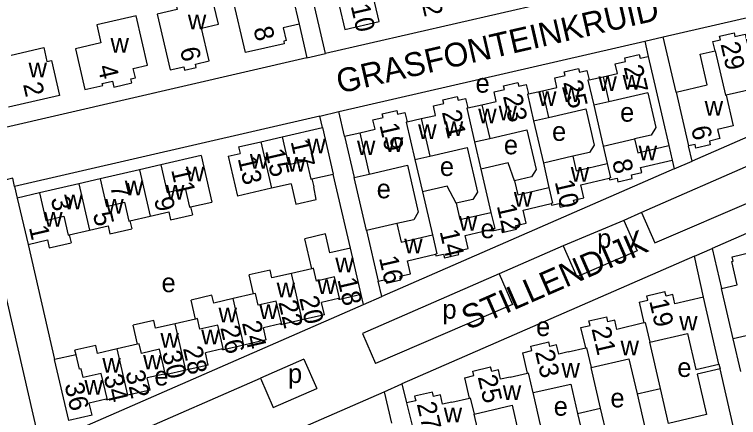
# Model space of a CAD drawing. Extents: x 155696 to 157795, y 382328 to 384028.
# Drawn here: x 157023.6 to 157175.4, y 383530 to 383614.6 of the extents above; entities that cross this region are included whole.
import ezdxf

# ---------------------------------------------------------------- set-up
doc = ezdxf.new("R2010")
doc.units = 0
for name, color, linetype in [('BLT_Basislijn', 7, 'Continuous'), ('BLT_Bebouwing', 7, 'Continuous'), ('BLT_Centroide', 7, 'Continuous'), ('BLT_Huisnummer', 7, 'Continuous'), ('BLT_Huisnummer_ tussenligend', 7, 'Continuous'), ('BLT_Onderverdeling_panden', 7, 'Continuous'), ('BLT_Straatnaam', 7, 'Continuous')]:
    doc.layers.add(name, color=color, linetype=linetype)

msp = doc.modelspace()

# ---------------------------------------------------------------- linework, layer by layer
at = {"layer": 'BLT_Basislijn'}
for p, q in [((157155.73, 383609.02), (157159.62, 383609.92)), ((157084.93, 383605.5), (157088.83, 383606.4)), ((157208.37, 383596.51), (157155.06, 383573.01)), ((157087.64, 383593.29), (157091.64, 383594.22)), ((157157.85, 383566.64), (157211.33, 383589.75)), ((157161.92, 383582.21), (157165.65, 383583.84)), ((157155.06, 383573.01), (157151.34, 383571.38)), ((157155.06, 383573.01), (157157.85, 383566.64)), ((157151.34, 383571.38), (157138.66, 383566.03)), ((157151.34, 383571.38), (157154.12, 383565.02)), ((157026.48, 383566.34), (157032.06, 383542.16)), ((157138.66, 383566.03), (157125.24, 383560.16)), ((157138.66, 383566.03), (157141.48, 383559.56)), ((157154.12, 383565.02), (157141.48, 383559.56)), ((157166.15, 383563.87), (157169.88, 383565.5)), ((157125.24, 383560.16), (157128.04, 383553.76)), ((157096.77, 383553.76), (157100.61, 383555.4)), ((157128.04, 383553.76), (157099.33, 383541.35)), ((157096.59, 383547.63), (157099.33, 383541.35)), ((157175.89, 383539.68), (157174.29, 383546.5)), ((157084.31, 383542.27), (157075.18, 383538.27)), ((157084.31, 383542.27), (157087.02, 383536.08)), ((157171.29, 383541.21), (157171.53, 383540.21)), ((157044.35, 383524.79), (157075.18, 383538.27)), ((157075.18, 383538.27), (157077.89, 383532.08)), ((157101.12, 383535.43), (157104.85, 383537.06)), ((157077.89, 383532.08), (157087.02, 383536.08))]:
    msp.add_line(p, q, dxfattribs=at)
for points in [[(157088.83, 383606.4), (157076, 383661.94)], [(157159.62, 383609.92), (157231.49, 383626.52)], [(157152.91, 383621.2), (157088.83, 383606.4)], [(157234.4, 383613.91), (157165.65, 383583.84), (157164.91, 383587.02)], [(157083.3, 383612.59), (157084.93, 383605.5)], [(157162.3, 383598.33), (157159.62, 383609.92)], [(157091.64, 383594.22), (157155.73, 383609.02)], [(157155.73, 383609.02), (157156.47, 383605.81)], [(157084.93, 383605.5), (157020.85, 383590.7)], [(157238.64, 383595.57), (157169.88, 383565.5), (157171.84, 383557.12)], [(157087.64, 383593.29), (157023.66, 383578.52)], [(157088.2, 383590.86), (157087.64, 383593.29)], [(157092.84, 383589.03), (157091.64, 383594.22)], [(157161.49, 383584.05), (157161.92, 383582.21)], [(157094.04, 383565.57), (157090.45, 383581.11)], [(157161.92, 383582.21), (157100.61, 383555.4)], [(157023.66, 383578.52), (157023.27, 383580.23), (157022.19, 383579.96), (157021.34, 383579.68), (157020.04, 383578.87), (157018.83, 383577.79), (157018.05, 383576.3), (157017.68, 383574.81), (157017.8, 383572.79), (157028.71, 383525.55)], [(157097.41, 383569.25), (157094.84, 383580.38)], [(157023.66, 383578.52), (157024.23, 383576.08)], [(157166.15, 383563.87), (157104.85, 383537.06)], [(157168.04, 383555.27), (157166.15, 383563.87)], [(157125.24, 383560.16), (157096.59, 383547.63)], [(157100.61, 383555.4), (157099.86, 383558.63)], [(157035.57, 383526.96), (157096.77, 383553.76), (157096.29, 383555.83)], [(157104.85, 383537.06), (157105.83, 383533.1)], [(157039.81, 383508.62), (157101.12, 383535.43), (157102.64, 383528.81)]]:
    msp.add_lwpolyline(points, dxfattribs=at)
at = {"layer": 'BLT_Bebouwing'}
for p, q in [((157079.91, 383627.27), (157083.3, 383612.59)), ((157022.95, 383606.06), (157029.77, 383607.64)), ((157029.77, 383607.64), (157030.44, 383604.71)), ((157030.44, 383604.71), (157031.42, 383604.94)), ((157031.42, 383604.94), (157033.1, 383597.63)), ((157048.55, 383603.25), (157051.53, 383603.94)), ((157049, 383601.3), (157048.55, 383603.25)), ((157048.05, 383601.08), (157049, 383601.3)), ((157048.25, 383600.23), (157048.05, 383601.08)), ((157038.4, 383598.85), (157042.14, 383599.72)), ((157042.04, 383600.12), (157044.17, 383600.61)), ((157042.14, 383599.72), (157042.04, 383600.12)), ((157044.17, 383600.61), (157044.46, 383599.35)), ((157044.46, 383599.35), (157048.25, 383600.23)), ((157033.1, 383597.63), (157022.39, 383595.15)), ((157162.3, 383598.33), (157164.91, 383587.02)), ((157145.05, 383595.57), (157147.04, 383586.97)), ((157132.45, 383592.25), (157134.49, 383583.41)), ((157079.76, 383588.91), (157088.2, 383590.86)), ((157088.2, 383590.86), (157090.45, 383581.11)), ((157075.29, 383587.87), (157079.76, 383588.91)), ((157070.61, 383586.8), (157075.29, 383587.87)), ((157120.09, 383587.86), (157121.41, 383582.15)), ((157070.61, 383586.8), (157070.93, 383585.43)), ((157062.77, 383584.98), (157054.33, 383583.03)), ((157062.77, 383584.98), (157065.02, 383575.24)), ((157068.44, 383584.86), (157070.93, 383585.43)), ((157068.44, 383584.86), (157070.38, 383576.48)), ((157107.57, 383584.15), (157109.14, 383577.37)), ((157054.33, 383583.03), (157049.86, 383582)), ((157049.86, 383582), (157041.61, 383580.1)), ((157085.98, 383580.08), (157090.45, 383581.11)), ((157041.61, 383580.1), (157037.14, 383579.06)), ((157085.98, 383580.08), (157086.36, 383578.43)), ((157037.14, 383579.06), (157028.9, 383577.16)), ((157077.54, 383578.13), (157070.38, 383576.48)), ((157081.64, 383579.08), (157077.54, 383578.13)), ((157086.9, 383575.78), (157086.36, 383578.43)), ((157028.9, 383577.16), (157024.23, 383576.08)), ((157024.23, 383576.08), (157026.48, 383566.34)), ((157060.55, 383574.21), (157065.02, 383575.24)), ((157060.55, 383574.21), (157060.93, 383572.56)), ((157047.83, 383571.27), (157052.11, 383572.26)), ((157052.11, 383572.26), (157055.99, 383573.15)), ((157055.99, 383573.15), (157056.37, 383571.51)), ((157056.37, 383571.51), (157060.93, 383572.56)), ((157047.83, 383571.27), (157048.21, 383569.62)), ((157035.12, 383568.33), (157039.39, 383569.32)), ((157039.39, 383569.32), (157043.28, 383570.22)), ((157043.28, 383570.22), (157043.66, 383568.57)), ((157043.66, 383568.57), (157048.21, 383569.62)), ((157026.48, 383566.34), (157030.56, 383567.28)), ((157030.56, 383567.28), (157030.94, 383565.63)), ((157035.12, 383568.33), (157035.5, 383566.69)), ((157088.86, 383568.53), (157084.52, 383567.52)), ((157085.94, 383561.24), (157084.52, 383567.52)), ((157089.76, 383564.58), (157088.86, 383568.53)), ((157030.94, 383565.63), (157035.5, 383566.69)), ((157094.04, 383565.57), (157089.76, 383564.58)), ((157096.29, 383555.83), (157094.04, 383565.57)), ((157085.94, 383561.24), (157081.67, 383560.25)), ((157077.2, 383560.95), (157072.84, 383559.94)), ((157073.77, 383555.96), (157072.84, 383559.94)), ((157077.58, 383559.3), (157077.2, 383560.95)), ((157081.67, 383560.25), (157077.58, 383559.3)), ((157174.29, 383546.5), (157171.84, 383557.12)), ((157065.02, 383555.68), (157060.67, 383554.67)), ((157065.41, 383554.03), (157065.02, 383555.68)), ((157073.77, 383555.96), (157069.49, 383554.97)), ((157096.29, 383555.83), (157091.82, 383554.79)), ((157061.59, 383550.68), (157060.67, 383554.67)), ((157069.49, 383554.97), (157065.41, 383554.03)), ((157091.57, 383554.96), (157088, 383554.14)), ((157088.59, 383551.58), (157088, 383554.14)), ((157091.62, 383554.75), (157091.57, 383554.96)), ((157091.82, 383554.79), (157091.62, 383554.75)), ((157061.59, 383550.68), (157057.32, 383549.7)), ((157088.59, 383551.58), (157083.92, 383550.51)), ((157052.85, 383550.4), (157048.49, 383549.39)), ((157049.42, 383545.41), (157048.49, 383549.39)), ((157053.23, 383548.75), (157052.85, 383550.4)), ((157057.32, 383549.7), (157053.23, 383548.75)), ((157079.4, 383549.69), (157075.83, 383548.86)), ((157079.45, 383549.47), (157079.4, 383549.69)), ((157079.65, 383549.52), (157079.45, 383549.47)), ((157083.92, 383550.51), (157079.65, 383549.52)), ((157076.42, 383546.31), (157075.83, 383548.86)), ((157076.42, 383546.31), (157071.74, 383545.23)), ((157040.67, 383545.12), (157036.32, 383544.12)), ((157041.06, 383543.48), (157040.67, 383545.12)), ((157049.42, 383545.41), (157045.14, 383544.42)), ((157071.74, 383545.23), (157067.47, 383544.24)), ((157036.55, 383543.2), (157032.06, 383542.16)), ((157036.55, 383543.2), (157036.32, 383544.12)), ((157045.14, 383544.42), (157041.06, 383543.48)), ((157067.22, 383544.41), (157063.65, 383543.59)), ((157064.24, 383541.03), (157063.65, 383543.59)), ((157067.27, 383544.2), (157067.22, 383544.41)), ((157067.47, 383544.24), (157067.27, 383544.2)), ((157035.02, 383529.36), (157032.06, 383542.16)), ((157059.57, 383539.95), (157055.3, 383538.97)), ((157064.24, 383541.03), (157059.57, 383539.95)), ((157055.05, 383539.14), (157051.48, 383538.31)), ((157055.1, 383538.92), (157055.05, 383539.14)), ((157055.3, 383538.97), (157055.1, 383538.92)), ((157052.07, 383535.76), (157051.48, 383538.31)), ((157052.07, 383535.76), (157047.39, 383534.68)), ((157047.39, 383534.68), (157043.12, 383533.69)), ((157042.87, 383533.86), (157039.3, 383533.03)), ((157039.89, 383530.48), (157039.3, 383533.03)), ((157042.92, 383533.65), (157042.87, 383533.86)), ((157043.12, 383533.69), (157042.92, 383533.65)), ((157105.83, 383533.1), (157107.72, 383525.43)), ((157039.89, 383530.48), (157035.02, 383529.36))]:
    msp.add_line(p, q, dxfattribs=at)
msp.add_lwpolyline([(157100.36, 383629.56), (157096.13, 383628.59), (157097.03, 383624.7), (157089.29, 383622.91), (157090.81, 383616.32), (157091.69, 383616.52), (157092.86, 383611.43), (157100.06, 383613.1), (157098.26, 383620.89), (157102.16, 383621.79)], close=True, dxfattribs=at)
for points in [[(157083.3, 383612.59), (157079.99, 383611.83), (157080.59, 383609.14), (157080.07, 383609.01), (157080.2, 383608.46), (157072.04, 383606.6), (157069.34, 383618.31), (157073.62, 383619.3), (157072.61, 383623.68), (157076.17, 383624.5), (157075.75, 383626.31), (157079.91, 383627.27)], [(157064.42, 383604.86), (157062.83, 383611.72), (157066.37, 383612.54), (157064.41, 383621), (157056.92, 383619.26), (157057.76, 383615.62), (157053.58, 383614.65), (157056.28, 383602.98), (157059.13, 383603.64), (157059.3, 383602.89), (157061.74, 383603.45), (157061.57, 383604.2), (157064.42, 383604.86)], [(157049.13, 383614.31), (157040.87, 383612.4), (157041.74, 383608.65), (157036.42, 383607.42), (157038.4, 383598.85)], [(157051.53, 383603.94), (157049.13, 383614.31)], [(157170.47, 383606.99), (157170.02, 383608.94), (157171.61, 383609.3), (157171.43, 383610.08), (157174.45, 383610.78), (157174.63, 383610), (157176.78, 383610.5), (157177.23, 383608.55), (157180.24, 383609.25), (157181.08, 383605.64)], [(157162.3, 383598.33), (157168.85, 383599.84), (157167.36, 383606.27), (157170.47, 383606.99)], [(157147, 383601.54), (157150.03, 383602.24), (157149.57, 383604.21), (157151.73, 383604.71), (157151.55, 383605.49), (157154.57, 383606.19), (157154.75, 383605.41), (157156.47, 383605.81)], [(157156.47, 383605.81), (157158.13, 383598.6)], [(157134.31, 383598.61), (157137.33, 383599.3), (157136.87, 383601.28), (157139.03, 383601.78), (157138.85, 383602.56), (157141.87, 383603.25), (157142.05, 383602.48), (157143.61, 383602.84), (157144.06, 383600.86)], [(157144.06, 383600.86), (157147, 383601.54)], [(157121.61, 383595.67), (157124.62, 383596.37), (157124.16, 383598.34), (157126.32, 383598.84), (157126.14, 383599.62), (157129.16, 383600.32), (157129.34, 383599.54), (157130.9, 383599.9), (157131.36, 383597.92)], [(157131.36, 383597.92), (157134.31, 383598.61)], [(157156.38, 383598.19), (157148.21, 383596.3)], [(157156.38, 383598.19), (157158.07, 383590.86), (157157.1, 383589.3), (157153.59, 383588.49)], [(157158.13, 383598.6), (157160.8, 383587.07)], [(157172.82, 383597.68), (157174.3, 383591.25), (157171, 383590.48), (157171.45, 383588.54), (157169.3, 383588.04), (157169.48, 383587.26), (157166.46, 383586.56), (157166.28, 383587.34), (157164.91, 383587.02)], [(157182.98, 383595.46), (157179.66, 383594.69), (157178.65, 383599.02), (157172.82, 383597.68)], [(157108.91, 383592.74), (157111.91, 383593.43), (157111.46, 383595.41), (157113.62, 383595.91), (157113.44, 383596.69), (157116.46, 383597.39), (157116.64, 383596.61), (157118.2, 383596.97), (157118.65, 383594.99)], [(157148.21, 383596.3), (157145.05, 383595.57)], [(157118.65, 383594.99), (157121.61, 383595.67)], [(157135.6, 383592.98), (157143.39, 383594.78)], [(157143.39, 383594.78), (157145.14, 383587.2), (157144.17, 383585.64), (157140.66, 383584.83)], [(157096, 383589.76), (157099.21, 383590.5), (157098.75, 383592.47), (157100.91, 383592.97), (157100.73, 383593.75), (157103.75, 383594.45), (157103.93, 383593.67), (157105.49, 383594.03), (157105.95, 383592.05)], [(157105.95, 383592.05), (157108.91, 383592.74)], [(157132.45, 383592.25), (157135.6, 383592.98)], [(157123.25, 383588.59), (157131.03, 383590.39)], [(157131.03, 383590.39), (157132.95, 383582.08), (157131.98, 383580.52), (157128.47, 383579.71)], [(157092.84, 383589.03), (157096, 383589.76)], [(157092.84, 383589.03), (157094.84, 383580.38)], [(157120.09, 383587.86), (157123.25, 383588.59)], [(157147.04, 383586.97), (157153.59, 383588.49)], [(157160.8, 383587.07), (157161.49, 383584.05)], [(157110.73, 383584.88), (157118.52, 383586.67)], [(157118.52, 383586.67), (157120.67, 383577.34), (157119.7, 383575.78), (157116.19, 383574.97)], [(157107.57, 383584.15), (157110.73, 383584.88)], [(157140.66, 383584.83), (157134.49, 383583.41)], [(157148.26, 383580.23), (157148.34, 383579.88), (157149.93, 383580.25), (157150.11, 383579.47), (157153.13, 383580.17), (157152.95, 383580.95), (157155.11, 383581.45), (157154.86, 383582.52), (157161.49, 383584.05)], [(157098, 383581.11), (157106, 383582.96)], [(157106, 383582.96), (157108.28, 383573.09), (157107.31, 383571.53), (157103.8, 383570.72)], [(157128.47, 383579.71), (157127.12, 383583.46), (157121.41, 383582.15)], [(157094.84, 383580.38), (157098, 383581.11)], [(157136.14, 383574.91), (157136.22, 383574.57), (157137.81, 383574.94), (157137.99, 383574.16), (157141.01, 383574.86), (157140.83, 383575.63), (157142.99, 383576.13), (157142.36, 383578.86), (157148.26, 383580.23)], [(157081.64, 383579.08), (157082.63, 383574.79), (157086.9, 383575.78)], [(157116.19, 383574.97), (157114.35, 383578.58), (157109.14, 383577.37)], [(157124.02, 383569.6), (157124.1, 383569.26), (157125.69, 383569.62), (157125.87, 383568.84), (157128.89, 383569.54), (157128.71, 383570.32), (157130.87, 383570.82), (157130.24, 383573.55), (157136.14, 383574.91)], [(157103.8, 383570.72), (157097.41, 383569.25)], [(157097.41, 383569.25), (157099.86, 383558.63)], [(157111.9, 383564.28), (157111.98, 383563.94), (157113.57, 383564.31), (157113.75, 383563.53), (157116.77, 383564.23), (157116.59, 383565.01), (157118.75, 383565.5), (157118.12, 383568.23), (157124.02, 383569.6)], [(157099.86, 383558.63), (157101.45, 383558.99), (157101.63, 383558.22), (157104.65, 383558.91), (157104.47, 383559.69), (157106.63, 383560.19), (157106, 383562.92), (157111.9, 383564.28)], [(157171.84, 383557.12), (157175.12, 383557.87), (157174, 383562.75), (157174.25, 383562.82), (157174.05, 383563.77), (157178.4, 383564.76)], [(157154.55, 383554.19), (157156.4, 383554.61), (157156.18, 383555.56), (157159.98, 383556.44)], [(157168.04, 383555.27), (157162.08, 383553.9), (157161.63, 383555.83), (157160.21, 383555.51), (157159.98, 383556.44)], [(157171.29, 383541.21), (157168.04, 383555.27)], [(157154.55, 383554.19), (157155.52, 383549.89)], [(157143.38, 383544.62), (157142.38, 383548.9), (157144.27, 383549.33), (157144.04, 383550.28), (157147.81, 383551.16)], [(157155.52, 383549.89), (157149.9, 383548.49), (157149.45, 383550.43), (157148.03, 383550.1), (157147.81, 383551.16)], [(157182.06, 383550.73), (157182.28, 383549.78), (157177.6, 383548.7), (157177.92, 383547.33), (157174.29, 383546.5)], [(157156.8, 383545.8), (157164.72, 383547.64), (157166.46, 383540.1), (157171.29, 383541.21)], [(157131.17, 383539.34), (157130.17, 383543.62), (157132.05, 383544.07), (157131.84, 383545.02), (157135.63, 383545.89)], [(157139.7, 383543.78), (157137.72, 383543.32), (157137.28, 383545.27), (157135.85, 383544.94), (157135.63, 383545.89)], [(157139.7, 383543.78), (157143.38, 383544.62)], [(157159.05, 383536.13), (157156.8, 383545.8)], [(157144.51, 383540.51), (157152.43, 383542.3), (157154.13, 383534.99)], [(157119.02, 383534.08), (157118.02, 383538.36), (157119.9, 383538.8), (157119.68, 383539.75), (157123.44, 383540.62)], [(157127.52, 383538.5), (157125.53, 383538.05), (157125.09, 383540), (157123.66, 383539.67), (157123.44, 383540.62)], [(157146.49, 383531.99), (157144.51, 383540.51)], [(157171.53, 383540.21), (157166.71, 383539.1), (157168.67, 383530.62), (157160.75, 383528.79)], [(157175, 383525.2), (157171.53, 383540.21)], [(157127.52, 383538.5), (157131.17, 383539.34)], [(157132.33, 383535.23), (157140.25, 383537.02), (157141.68, 383530.87)], [(157160.75, 383528.79), (157159.05, 383536.13)], [(157111.28, 383535.36), (157107.5, 383534.48), (157107.73, 383533.53), (157105.83, 383533.1)], [(157115.33, 383533.24), (157113.36, 383532.79), (157112.93, 383534.74), (157111.5, 383534.41), (157111.28, 383535.36)], [(157115.33, 383533.24), (157119.02, 383534.08)], [(157134.04, 383527.86), (157132.33, 383535.23)], [(157154.13, 383534.99), (157155.83, 383527.63), (157147.91, 383525.84)], [(157120.01, 383530.73), (157127.92, 383532.57), (157129.26, 383526.75)], [(157141.68, 383530.88), (157143.12, 383524.69), (157135.2, 383522.89)], [(157147.91, 383525.84), (157146.49, 383531.99)], [(157121.61, 383523.78), (157120.01, 383530.73)]]:
    msp.add_lwpolyline(points, dxfattribs=at)
at = {"layer": 'BLT_Onderverdeling_panden'}
for p, q in [((157079.76, 383588.91), (157081.1, 383583.12)), ((157075.29, 383587.87), (157077.54, 383578.13)), ((157081.1, 383583.12), (157084.87, 383583.99)), ((157084.87, 383583.99), (157085.78, 383580.04)), ((157054.33, 383583.03), (157055.66, 383577.25)), ((157049.86, 383582), (157052.11, 383572.26)), ((157121.41, 383582.15), (157123.51, 383573.07)), ((157041.61, 383580.1), (157042.95, 383574.31)), ((157085.78, 383580.04), (157085.98, 383580.08)), ((157037.14, 383579.06), (157039.39, 383569.32)), ((157055.66, 383577.25), (157059.44, 383578.12)), ((157059.44, 383578.12), (157060.35, 383574.16)), ((157028.9, 383577.16), (157030.23, 383571.37)), ((157109.14, 383577.37), (157111.23, 383568.33)), ((157042.95, 383574.31), (157046.72, 383575.18)), ((157046.72, 383575.18), (157047.63, 383571.22)), ((157060.35, 383574.16), (157060.55, 383574.21)), ((157030.23, 383571.37), (157034.01, 383572.24)), ((157034.01, 383572.24), (157034.92, 383568.29)), ((157047.63, 383571.22), (157047.83, 383571.27)), ((157034.92, 383568.29), (157035.12, 383568.33)), ((157086.34, 383561.33), (157085.94, 383561.24)), ((157086.96, 383558.65), (157086.34, 383561.33)), ((157083.92, 383550.51), (157081.67, 383560.25)), ((157090.73, 383559.52), (157086.96, 383558.65)), ((157091.82, 383554.79), (157090.73, 383559.52)), ((157074.16, 383556.05), (157073.77, 383555.96)), ((157074.73, 383553.59), (157074.16, 383556.05)), ((157071.74, 383545.23), (157069.49, 383554.97)), ((157078.5, 383554.46), (157074.73, 383553.59)), ((157079.65, 383549.52), (157078.5, 383554.46)), ((157061.99, 383550.78), (157061.59, 383550.68)), ((157062.51, 383548.53), (157061.99, 383550.78)), ((157059.57, 383539.95), (157057.32, 383549.7)), ((157066.28, 383549.4), (157062.51, 383548.53)), ((157067.47, 383544.24), (157066.28, 383549.4)), ((157049.81, 383545.5), (157049.42, 383545.41)), ((157050.28, 383543.47), (157049.81, 383545.5)), ((157047.39, 383534.68), (157045.14, 383544.42)), ((157054.05, 383544.34), (157050.28, 383543.47)), ((157055.3, 383538.97), (157054.05, 383544.34)), ((157038.06, 383538.41), (157037.64, 383540.23)), ((157041.83, 383539.28), (157038.06, 383538.41)), ((157043.12, 383533.69), (157041.83, 383539.28))]:
    msp.add_line(p, q, dxfattribs=at)
for points in [[(157170.47, 383606.99), (157170.53, 383607), (157172.7, 383597.65), (157172.82, 383597.68)], [(157144.06, 383600.86), (157143.84, 383600.81), (157145.05, 383595.57)], [(157147, 383601.54), (157148.21, 383596.3)], [(157131.36, 383597.92), (157131.15, 383597.88), (157132.45, 383592.25)], [(157134.31, 383598.61), (157135.6, 383592.98)], [(157118.65, 383594.99), (157118.45, 383594.94), (157120.09, 383587.86)], [(157121.61, 383595.67), (157123.25, 383588.59)], [(157105.95, 383592.05), (157105.76, 383592.01), (157107.57, 383584.15)], [(157108.91, 383592.74), (157110.73, 383584.88)], [(157096, 383589.76), (157098, 383581.11)], [(157153.59, 383588.49), (157154.27, 383585.56)], [(157154.27, 383585.56), (157160.8, 383587.07)], [(157147.04, 383586.97), (157147.88, 383583.32)], [(157140.66, 383584.83), (157141.36, 383581.81), (157147.88, 383583.32)], [(157134.49, 383583.41), (157135.67, 383578.29)], [(157147.88, 383583.32), (157148.58, 383580.3), (157148.26, 383580.23)], [(157128.47, 383579.71), (157129.14, 383576.78), (157135.67, 383578.29)], [(157135.67, 383578.29), (157136.44, 383574.98), (157136.14, 383574.91)], [(157116.19, 383574.97), (157116.98, 383571.56), (157123.51, 383573.07)], [(157123.51, 383573.07), (157124.29, 383569.66), (157124.02, 383569.6)], [(157103.8, 383570.72), (157104.7, 383566.83), (157111.23, 383568.33)], [(157111.23, 383568.33), (157112.15, 383564.34), (157111.9, 383564.28)], [(157155.52, 383549.89), (157155.85, 383549.97), (157156.8, 383545.8)], [(157143.38, 383544.62), (157143.55, 383544.66), (157144.5, 383540.51), (157144.51, 383540.51)], [(157037.64, 383540.23), (157037.24, 383540.13), (157036.55, 383543.2)], [(157131.17, 383539.34), (157131.34, 383539.38), (157132.3, 383535.22), (157132.33, 383535.23)], [(157154.13, 383534.99), (157159.05, 383536.13)], [(157119.02, 383534.08), (157119.18, 383534.12), (157119.97, 383530.72), (157120.01, 383530.73)], [(157141.68, 383530.88), (157146.49, 383531.99)]]:
    msp.add_lwpolyline(points, dxfattribs=at)

# ---------------------------------------------------------------- texts
at = {"layer": 'BLT_Centroide'}
for s, p in [('w', (157059.98, 383611.5)), ('w', (157043.77, 383606.59)), ('w', (157026.59, 383601.41)), ('e', (157120.28, 383598.19)), ('w', (157146.03, 383598.56)), ('w', (157151.1, 383598.82)), ('w', (157138.42, 383596.26)), ('w', (157133.38, 383595.42)), ('w', (157168.3, 383593.36)), ('w', (157120.84, 383591.77)), ('w', (157125.1, 383592.42)), ('e', (157150.57, 383592.1)), ('w', (157113.83, 383589.09)), ('w', (157108.25, 383588.45)), ('e', (157136.31, 383588.08)), ('w', (157101.28, 383585.76)), ('w', (157085.01, 383585.44)), ('w', (157095.42, 383585.08)), ('e', (157126.21, 383585.25)), ('w', (157154.46, 383583.97)), ('w', (157072.98, 383582.22)), ('w', (157080.83, 383581.59)), ('w', (157059.57, 383579.56)), ('e', (157112.8, 383580.71)), ('w', (157140.24, 383579.5)), ('w', (157046.76, 383576.62)), ('w', (157055.39, 383575.73)), ('e', (157099.56, 383576.02)), ('w', (157034.05, 383573.69)), ('w', (157128.31, 383574.28)), ('w', (157042.67, 383572.8)), ('w', (157029.86, 383570.05)), ('w', (157116.77, 383569.25)), ('e', (157121.31, 383567.65)), ('w', (157105.32, 383564.47)), ('p', (157145.76, 383565.59)), ('w', (157090.88, 383560.5)), ('e', (157054.46, 383556.32)), ('w', (157078.59, 383555.25)), ('w', (157087.12, 383555.91)), ('w', (157074.95, 383550.66)), ('p', (157113.34, 383550.75)), ('w', (157066.41, 383549.97)), ('w', (157162.95, 383548.28)), ('e', (157132.97, 383547.11)), ('w', (157054.23, 383544.69)), ('w', (157062.77, 383545.38)), ('w', (157150.67, 383543.06)), ('w', (157050.59, 383540.09)), ('w', (157042.06, 383539.41)), ('e', (157162.57, 383538.53)), ('p', (157080.96, 383537.26)), ('w', (157138.29, 383538.38)), ('e', (157052.96, 383536.73)), ('w', (157038.31, 383534.78)), ('w', (157125.98, 383533.69)), ('e', (157148.54, 383532.14)), ('e', (157136.66, 383530.39)), ('w', (157113.61, 383529.03))]:
    msp.add_text(s, height=4, dxfattribs=at).set_placement(p)
at = {"layer": 'BLT_Huisnummer'}
for s, rotation, p in [('12', 283.0027, (157108.34, 383619.71)), ('10', 283.0069, (157094.08, 383616.42)), ('8', 283.0069, (157073.7, 383611.64)), ('29', 283.0063, (157171.6, 383608.4)), ('6', 283.0106, (157058.28, 383607.33)), ('4', 283.0106, (157041.04, 383603.65)), ('27', 283.0059, (157151.3, 383603.58)), ('2', 282.9751, (157025.42, 383599.95)), ('23', 283.0059, (157126, 383597.49)), ('19', 283.0059, (157100.11, 383591.4)), ('6', 283.0063, (157165.41, 383590.81)), ('17', 283.0051, (157081.49, 383587.95)), ('13', 283.0051, (157070.41, 383584.37)), ('8', 283.0059, (157148.88, 383583.79)), ('11', 283.007, (157056.45, 383581.99)), ('7', 283.007, (157043.66, 383578.61)), ('3', 283.007, (157031.21, 383575.96)), ('12', 283.0059, (157124.71, 383574.44)), ('1', 283.007, (157026.64, 383569.92)), ('16', 283.0059, (157100.01, 383563.53)), ('18', 283.007, (157091.31, 383558.98)), ('20', 283.007, (157083.31, 383555.1)), ('19', 283.0065, (157156.65, 383554.49)), ('24', 283.007, (157071.29, 383549.88)), ('28', 283.007, (157058.94, 383544.54)), ('23', 283.0065, (157132.73, 383543.82)), ('32', 283.007, (157046.87, 383539.52)), ('36', 283.007, (157034.1, 383536.92)), ('27', 283.0065, (157107.95, 383532.86))]:
    msp.add_text(s, height=4, rotation=rotation, dxfattribs=at).set_placement(p)
at = {"layer": 'BLT_Huisnummer_ tussenligend'}
for s, rotation, p in [('25', 283.0059, (157138.64, 383600.4)), ('21', 283.0059, (157113.19, 383594.12)), ('15', 283.0051, (157076.16, 383586.01)), ('10', 283.0059, (157136.85, 383579.5)), ('9', 283.007, (157052.86, 383575.85)), ('5', 283.007, (157040.04, 383572.76)), ('14', 283.0059, (157112.73, 383569.08)), ('22', 283.007, (157078.93, 383554.22)), ('26', 283.007, (157066.76, 383548.88)), ('21', 283.0065, (157144.56, 383548.64)), ('30', 283.007, (157054.52, 383543.64)), ('34', 283.007, (157042.3, 383538.69)), ('25', 283.0065, (157120.71, 383538.53))]:
    msp.add_text(s, height=4, rotation=rotation, dxfattribs=at).set_placement(p)
at = {"layer": 'BLT_Straatnaam'}
for s, rotation, p in [('GRASFONTEINKRUID', 13.0072, (157091.76, 383597.99)), ('STILLENDIJK', 23.6196, (157118.72, 383548.31))]:
    msp.add_text(s, height=5, rotation=rotation, dxfattribs=at).set_placement(p)

doc.saveas('drawing.dxf')
